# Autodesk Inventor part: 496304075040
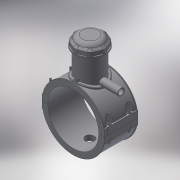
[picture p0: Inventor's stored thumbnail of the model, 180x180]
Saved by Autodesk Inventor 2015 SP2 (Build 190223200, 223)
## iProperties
Created: 2017-07
Part Number: 496304075040
Material: Generic
Description: PLASSON TAPPING SADDLE 75x40
Document SubType Name: Modeling
Designer: KIM
Mass: 692.316 g
Surface Area: 1723.22 cm^2
Volume: 692.316 cm^3
Density: 1 g/cm^3
Appearance: Default
Author: KIM
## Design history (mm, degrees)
derived "496304.ipt"
feature "Solid1::496304.ipt"
feature "Solid2::496304.ipt"
feature "Solid4::496304.ipt"
feature "Solid5::496304.ipt"
tag "TaggingFeature1"
body "Solid1"
body "Solid2"
other parameters: "d0" = 75, "d2" = 117, "d3" = 18.75, "d4" = 118, "d5" = 0, "d6" = 0.1, "d8" = 0, "d19" = 6, "d20" = 6, "d21" = 70.8, "d23" = 0, "d24" = 35.4, "d26" = 0, "d29" = 3, "d30" = 25, "d31" = 6, "d32" = 0, "d33" = 0, "d34" = 0.6, "d40" = 50.7, "d41" = 67.5, "d43" = 0, "d45" = 0, "d47" = 119.55, "d70" = 15, "d72" = 0, "d73" = 6, "d75" = 5, "d76" = 0, "d77" = 3.75, "d78" = 67.5, "d79" = 15, "d80" = 47.2, "d82" = 5 deg, "d84" = 4, "d85" = 14, "d86" = 0, "d87" = 3, "d88" = 0, "d89" = 1, "d90" = 1, "d91" = 94.4, "d92" = 0, "d93" = 0.5, "d94" = 39.47368, "d96" = 99.45, "d97" = 2.36, "d98" = 0, "d102" = 0.75, "d120" = 140 deg, "d121" = 24.228, "d122" = 20 deg, "d123" = 195, "d124" = 58.5, "d126" = 0, "d143" = 77.25, "d145" = 17.30769, "d149" = 1.125, "d150" = 19.03846, "d153" = 118, "d154" = 0, "d156" = 48.75, "d157" = 160 deg, "d159" = 4.5, "d161" = 1.125, "d162" = 70.8, "d163" = 0, "d164" = 37.5, "d167" = 7.5, "d168" = 47.56098, "d170" = 3.375, "d172" = 0, "d173" = 1, "d175" = 37.5, "d176" = 20 deg, "d177" = 5.25, "d178" = 22.5, "d180" = 0, "d183" = 9, "d184" = 4.2, "d185" = 38.35, "d186" = 38.35, "d187" = 48.75, "d188" = 6.75, "d189" = 5.25, "d190" = 0, "d191" = 73.125, "d193" = 6.3, "d194" = 4.13, "d195" = 90 deg, "d197" = 0, "d199" = 0, "d200" = 11.25, "d202" = 0, "d203" = 177, "d204" = 64.125, "d205" = 47.25, "d206" = 57.375, "d207" = 132.75, "d208" = 138.06, "d209" = 164.61, "d210" = 58.05, "d211" = 67.5, "d212" = 54, "d213" = 36, "d216" = 0, "d217" = 7.5, "d218" = 7.5, "d219" = 1.5, "d222" = 75, "d224" = 0, "d230" = 4.5, "d233" = 6, "d236" = 58.5, "d237" = 35.4, "d238" = 6.02433, "d240" = 35.4, "d241" = 35.4, "d242" = 35.4, "d243" = 6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
